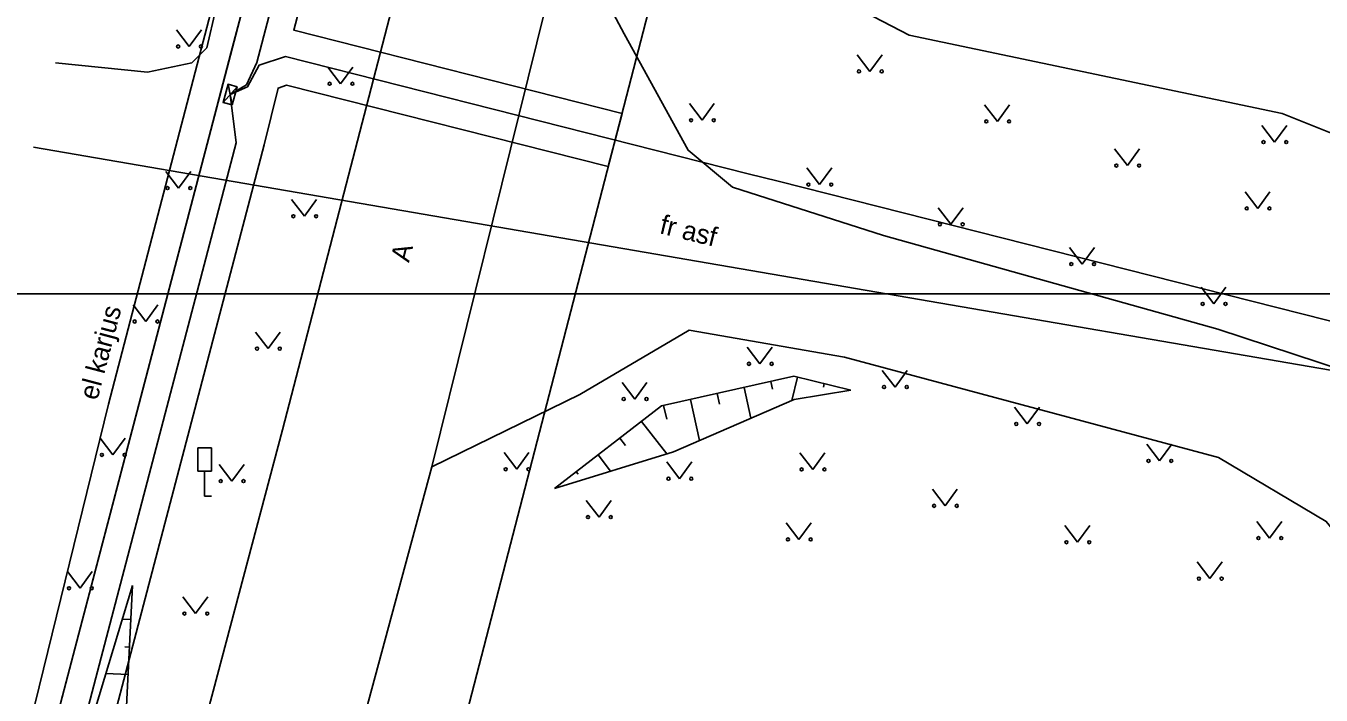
# Model space of a CAD drawing. Extents: x 554947 to 555436, y 6564938 to 6565792.
# Drawn here: x 555148.42 to 555195.59, y 6565133.31 to 6565157.67 of the extents above; entities that cross this region are included whole.
import ezdxf

# ---------------------------------------------------------------- set-up
doc = ezdxf.new("R2010")
doc.units = 0
for name, color, linetype in [('AED', 7, 'Continuous'), ('HALJASTUS', 7, 'Continuous'), ('KASUTUSALA', 7, 'Continuous'), ('KPKAABEL', 7, 'Continuous'), ('KPOHULIIN', 7, 'Continuous'), ('LIIKLUS', 7, 'Continuous'), ('PIIR', 7, 'Continuous'), ('PR_SIDE', 7, 'Continuous'), ('RELJEEF', 7, 'Continuous'), ('TEE', 7, 'Continuous'), ('VORMISTUS_1', 7, 'Continuous')]:
    doc.layers.add(name, color=color, linetype=linetype)

msp = doc.modelspace()

# ---------------------------------------------------------------- linework, layer by layer
at = {"layer": 'AED'}
msp.add_lwpolyline([(555179.37, 6565300.078), (555180.242, 6565299.846), (555180.75, 6565290.874), (555180.137, 6565280.616), (555178.982, 6565264.788), (555177.984, 6565255.288), (555177.306, 6565249.05), (555173.486, 6565227.422), (555169.733, 6565212.423), (555163.779, 6565189.534), (555156.086, 6565161.758), (555151.428, 6565143.905), (555146.995, 6565125.891), (555142.273, 6565107.514), (555136.767, 6565086.759), (555131.214, 6565064.984), (555128.386, 6565056.617), (555127.142, 6565056.522)], dxfattribs=at)
at = {"layer": 'HALJASTUS'}
for p, q in [((555153.905, 6565157.527), (555154.369, 6565156.92)), ((555154.369, 6565156.92), (555154.814, 6565157.527)), ((555178.697, 6565156.621), (555179.16, 6565156.014)), ((555179.16, 6565156.014), (555179.606, 6565156.621)), ((555159.422, 6565156.171), (555159.885, 6565155.564)), ((555159.885, 6565155.564), (555160.331, 6565156.171)), ((555172.582, 6565154.843), (555173.046, 6565154.237)), ((555173.046, 6565154.237), (555173.491, 6565154.843)), ((555183.335, 6565154.799), (555183.798, 6565154.192)), ((555183.798, 6565154.192), (555184.244, 6565154.799)), ((555193.428, 6565154.044), (555193.891, 6565153.438)), ((555193.891, 6565153.438), (555194.337, 6565154.044)), ((555188.069, 6565153.192), (555188.533, 6565152.586)), ((555188.533, 6565152.586), (555188.978, 6565153.192)), ((555176.858, 6565152.501), (555177.321, 6565151.895)), ((555177.321, 6565151.895), (555177.767, 6565152.501)), ((555153.519, 6565152.37), (555153.983, 6565151.764)), ((555153.983, 6565151.764), (555154.428, 6565152.37)), ((555192.817, 6565151.631), (555193.281, 6565151.024)), ((555193.281, 6565151.024), (555193.726, 6565151.631)), ((555158.1, 6565151.349), (555158.563, 6565150.742)), ((555158.563, 6565150.742), (555159.009, 6565151.349)), ((555181.643, 6565151.053), (555182.107, 6565150.447)), ((555182.107, 6565150.447), (555182.552, 6565151.053)), ((555186.429, 6565149.605), (555186.892, 6565148.998)), ((555186.892, 6565148.998), (555187.338, 6565149.605)), ((555191.215, 6565148.157), (555191.678, 6565147.55)), ((555191.678, 6565147.55), (555192.124, 6565148.157)), ((555152.323, 6565147.515), (555152.787, 6565146.909)), ((555152.787, 6565146.909), (555153.232, 6565147.515)), ((555156.778, 6565146.526), (555157.241, 6565145.92)), ((555157.241, 6565145.92), (555157.687, 6565146.526)), ((555174.691, 6565145.974), (555175.155, 6565145.368)), ((555175.155, 6565145.368), (555175.6, 6565145.974)), ((555179.609, 6565145.131), (555180.072, 6565144.524)), ((555180.072, 6565144.524), (555180.518, 6565145.131)), ((555170.131, 6565144.692), (555170.594, 6565144.086)), ((555170.594, 6565144.086), (555171.04, 6565144.692)), ((555184.425, 6565143.785), (555184.888, 6565143.179)), ((555184.888, 6565143.179), (555185.334, 6565143.785)), ((555151.127, 6565142.66), (555151.591, 6565142.054)), ((555151.591, 6565142.054), (555152.036, 6565142.66)), ((555165.834, 6565142.136), (555166.297, 6565141.53)), ((555166.297, 6565141.53), (555166.743, 6565142.136)), ((555176.61, 6565142.129), (555177.073, 6565141.523)), ((555177.073, 6565141.523), (555177.519, 6565142.129)), ((555189.24, 6565142.44), (555189.703, 6565141.833)), ((555189.703, 6565141.833), (555190.149, 6565142.44)), ((555155.456, 6565141.704), (555155.919, 6565141.098)), ((555155.919, 6565141.098), (555156.365, 6565141.704)), ((555171.761, 6565141.794), (555172.224, 6565141.187)), ((555172.224, 6565141.187), (555172.67, 6565141.794)), ((555181.431, 6565140.804), (555181.895, 6565140.198)), ((555181.895, 6565140.198), (555182.34, 6565140.804)), ((555168.829, 6565140.394), (555169.293, 6565139.788)), ((555169.293, 6565139.788), (555169.738, 6565140.394)), ((555176.111, 6565139.581), (555176.574, 6565138.974)), ((555176.574, 6565138.974), (555177.02, 6565139.581)), ((555186.252, 6565139.479), (555186.716, 6565138.872)), ((555186.716, 6565138.872), (555187.161, 6565139.479)), ((555193.244, 6565139.631), (555193.707, 6565139.024)), ((555193.707, 6565139.024), (555194.152, 6565139.631)), ((555191.074, 6565138.154), (555191.537, 6565137.547)), ((555191.537, 6565137.547), (555191.983, 6565138.154)), ((555149.932, 6565137.806), (555150.395, 6565137.199)), ((555150.395, 6565137.199), (555150.841, 6565137.806)), ((555154.134, 6565136.882), (555154.598, 6565136.276)), ((555154.598, 6565136.276), (555155.043, 6565136.882))]:
    msp.add_line(p, q, dxfattribs=at)
msp.add_lwpolyline([(555170.849, 6565163.433), (555170.802, 6565162.422), (555180.588, 6565157.338), (555194.166, 6565154.476), (555200.547, 6565151.934), (555210.105, 6565148.383), (555222.421, 6565148.556), (555228.239, 6565151.421), (555231.104, 6565153.786)], dxfattribs=at)
for centre in [(555153.968, 6565156.92), (555154.796, 6565156.92), (555178.759, 6565156.014), (555179.588, 6565156.014), (555159.484, 6565155.564), (555160.313, 6565155.564), (555172.645, 6565154.237), (555173.473, 6565154.237), (555183.397, 6565154.192), (555184.226, 6565154.192), (555193.49, 6565153.438), (555194.319, 6565153.438), (555188.132, 6565152.586), (555188.961, 6565152.586), (555153.582, 6565151.764), (555154.41, 6565151.764), (555176.92, 6565151.895), (555177.749, 6565151.895), (555192.88, 6565151.024), (555193.708, 6565151.024), (555158.162, 6565150.742), (555158.991, 6565150.742), (555181.706, 6565150.447), (555182.534, 6565150.447), (555186.491, 6565148.998), (555187.32, 6565148.998), (555191.277, 6565147.55), (555192.106, 6565147.55), (555152.386, 6565146.909), (555153.214, 6565146.909), (555156.84, 6565145.92), (555157.669, 6565145.92), (555174.754, 6565145.368), (555175.582, 6565145.368), (555179.671, 6565144.524), (555180.5, 6565144.524), (555170.193, 6565144.086), (555171.022, 6565144.086), (555184.487, 6565143.179), (555185.316, 6565143.179), (555151.19, 6565142.054), (555152.019, 6565142.054), (555165.896, 6565141.53), (555166.725, 6565141.53), (555189.302, 6565141.833), (555190.131, 6565141.833), (555155.518, 6565141.098), (555156.347, 6565141.098), (555171.823, 6565141.187), (555172.652, 6565141.187), (555176.672, 6565141.523), (555177.501, 6565141.523), (555181.494, 6565140.198), (555182.322, 6565140.198), (555168.892, 6565139.788), (555169.721, 6565139.788), (555176.173, 6565138.974), (555177.002, 6565138.974), (555186.315, 6565138.872), (555187.144, 6565138.872), (555193.306, 6565139.024), (555194.135, 6565139.024), (555191.136, 6565137.547), (555191.965, 6565137.547), (555149.994, 6565137.199), (555150.823, 6565137.199), (555154.197, 6565136.276), (555155.025, 6565136.276)]:
    msp.add_circle(centre, 0.055, dxfattribs=at)
at = {"layer": 'KASUTUSALA'}
for points in [[(555127.058, 6565046.777), (555141.002, 6565099.93), (555152.728, 6565144.628), (555155.084, 6565153.611), (555155.888, 6565156.675), (555156.912, 6565160.576), (555162.414, 6565181.549), (555172.651, 6565220.574), (555172.7, 6565220.76), (555176.927, 6565240.07), (555176.937, 6565240.135), (555179.22, 6565254.85)], [(555181.208, 6565254.618), (555178.897, 6565239.723), (555174.645, 6565220.292), (555158.175, 6565157.509), (555170.133, 6565154.484), (555169.631, 6565152.548), (555157.917, 6565155.511), (555157.606, 6565155.409), (555157.1, 6565153.341), (555146.607, 6565113.414), (555140.881, 6565091.587), (555138.365, 6565081.691), (555135.803, 6565072.229), (555119.022, 6565008.261)]]:
    msp.add_lwpolyline(points, dxfattribs=at)
at = {"layer": 'KPKAABEL'}
msp.add_lwpolyline([(555172.536, 6565254.014), (555171.281, 6565241.464), (555170.488, 6565231.192), (555168.866, 6565217.1), (555167.048, 6565204.461), (555164.351, 6565191.399), (555161.107, 6565179.306), (555157.628, 6565168.142), (555155.008, 6565156.873), (555154.465, 6565156.331), (555152.85, 6565155.986), (555149.5, 6565156.323)], dxfattribs=at)
at = {"layer": 'KPOHULIIN'}
msp.add_lwpolyline([(555148.701, 6565153.258), (555226.644, 6565139.855), (555319.309, 6565121.586)], dxfattribs=at)
at = {"layer": 'LIIKLUS'}
for p, q in [((555154.681, 6565142.306), (555154.681, 6565141.457)), ((555155.181, 6565142.306), (555154.681, 6565142.306)), ((555155.181, 6565142.306), (555155.181, 6565141.457)), ((555155.181, 6565141.457), (555154.681, 6565141.457)), ((555154.931, 6565141.457), (555154.931, 6565140.556)), ((555155.181, 6565140.556), (555154.931, 6565140.556))]:
    msp.add_line(p, q, dxfattribs=at)
at = {"layer": 'PIIR'}
msp.add_lwpolyline([(554962.55, 6565234.93), (555180.26, 6565306.43), (555180.8, 6565287.7), (555180.41, 6565269.99), (555179.22, 6565254.85), (555176.93, 6565240.09), (555172.7, 6565220.76), (555117.14, 6565008.97), (555108.27, 6564991.27)], close=True, dxfattribs=at)
for points in [[(555195.28, 6565271.63), (555191.64, 6565237.48), (555173.84, 6565168.77), (555173.21, 6565166.35), (555172.58, 6565163.93), (555140.74, 6565041.04), (555133.32, 6565012.53), (555119.68, 6564972.95), (555107.79, 6564965.53), (555093.78, 6564958.98), (555080.97, 6564954.71), (555029.586, 6564944.201)], [(555029.586, 6564962.189), (555076.32, 6564971.61), (555087.28, 6564975.26), (555098.22, 6564980.37), (555106.03, 6564987.06), (555108.27, 6564991.27), (555117.14, 6565008.97), (555172.7, 6565220.76), (555176.93, 6565240.09), (555179.22, 6565254.85)], [(555272.013, 6565013.369), (555140.74, 6565041.04), (555172.58, 6565163.93), (555173.21, 6565166.35), (555225.89, 6565157.13), (555231.12, 6565150.64), (555239.11, 6565139), (555273.15, 6565087.34), (555275.41, 6565088.83), (555288.85, 6565092.31), (555289.83, 6565088.53), (555290.166, 6565088.221)]]:
    msp.add_lwpolyline(points, dxfattribs=at)
at = {"layer": 'PR_SIDE'}
for p, q in [((555156.116, 6565155.457), (555155.601, 6565154.883)), ((555155.934, 6565154.792), (555155.784, 6565155.548))]:
    msp.add_line(p, q, dxfattribs=at)
for points in [[(555210.992, 6564988.671), (555132.015, 6564980.717), (555127.536, 6564982.26), (555122.65, 6564985.013), (555110.837, 6564991.67), (555110.25, 6564992.989), (555118.081, 6565008.615), (555124.872, 6565034.501), (555128.062, 6565046.662), (555134.837, 6565072.487), (555137.397, 6565081.944), (555139.913, 6565091.837), (555145.64, 6565113.668), (555156.083, 6565153.408), (555155.859, 6565155.17), (555156.452, 6565155.519), (555156.834, 6565156.34), (555160.763, 6565171.317), (555163.707, 6565182.54), (555165.376, 6565188.901), (555173.672, 6565220.526), (555176.862, 6565235.1), (555177.913, 6565239.906), (555180.214, 6565254.734)], [(555239.586, 6565136.265), (555231.314, 6565137.915), (555222.994, 6565144.574), (555217.72, 6565147.16), (555203.944, 6565144.9), (555175.818, 6565152.015), (555174.729, 6565152.29), (555157.882, 6565156.552), (555156.917, 6565156.236), (555156.491, 6565155.453), (555155.859, 6565155.17)]]:
    msp.add_lwpolyline(points, dxfattribs=at)
msp.add_lwpolyline([(555155.934, 6565154.792), (555156.116, 6565155.457), (555155.784, 6565155.548), (555155.601, 6565154.883)], close=True, dxfattribs=at)
at = {"layer": 'RELJEEF'}
for p, q in [((555174.573, 6565144.51), (555174.824, 6565143.386)), ((555175.549, 6565144.729), (555175.612, 6565144.448)), ((555176.524, 6565144.881), (555176.32, 6565144.035)), ((555177.496, 6565144.646), (555177.467, 6565144.524)), ((555172.621, 6565144.074), (555172.956, 6565142.576)), ((555173.597, 6565144.292), (555173.685, 6565143.899)), ((555171.645, 6565143.855), (555171.758, 6565143.35)), ((555170.84, 6565143.274), (555171.757, 6565142.086)), ((555170.048, 6565142.663), (555170.255, 6565142.396)), ((555169.257, 6565142.052), (555169.716, 6565141.458)), ((555168.465, 6565141.44), (555168.534, 6565141.351)), ((555152.292, 6565137.054), (555152.273, 6565137.055)), ((555152.242, 6565136.056), (555151.932, 6565136.071)), ((555152.192, 6565135.057), (555152.024, 6565135.065)), ((555152.142, 6565134.058), (555151.334, 6565134.099))]:
    msp.add_line(p, q, dxfattribs=at)
for points in [[(555167.674, 6565140.829), (555171.571, 6565143.839), (555176.382, 6565144.915), (555178.457, 6565144.415)], [(555167.674, 6565140.829), (555172, 6565142.161), (555176.401, 6565144.071), (555178.457, 6565144.415)], [(555119.659, 6565010.325), (555123.707, 6565025.312), (555129.009, 6565045.265), (555134.764, 6565064.612), (555140.243, 6565085.297), (555145.723, 6565106.564), (555150.38, 6565124.533), (555151.998, 6565131.189), (555152.304, 6565137.301)], [(555119.659, 6565010.325), (555122.574, 6565025.466), (555127.459, 6565046.429), (555133.335, 6565064.856), (555138.641, 6565085.815), (555144.363, 6565106.834), (555149.086, 6565124.763), (555150.576, 6565131.594), (555152.304, 6565137.301)]]:
    msp.add_lwpolyline(points, dxfattribs=at)
at = {"layer": 'TEE'}
for points in [[(555183.594, 6565248.995), (555179.697, 6565227.862), (555175.388, 6565210.507), (555169.433, 6565187.479), (555162.32, 6565160.507), (555157.772, 6565142.96), (555152.674, 6565123.751), (555148.003, 6565106.069), (555142.307, 6565084.705), (555136.784, 6565063.937), (555131.82, 6565044.704), (555126.529, 6565024.437), (555123.003, 6565010.821), (555119.083, 6564999.093), (555116.16, 6564993.195), (555108.256, 6564982.259)], [(555114.997, 6564980.207), (555119.473, 6564986.791), (555121.429, 6564990.442), (555124.132, 6564996.667), (555128.448, 6565009.121), (555131.982, 6565022.769), (555137.234, 6565043.213), (555142.087, 6565062.036), (555147.465, 6565082.979), (555153.125, 6565104.459), (555157.981, 6565122.311), (555163.2, 6565141.618), (555168.3, 6565162.209), (555168.744, 6565163.563), (555174.483, 6565185.521), (555180.709, 6565208.971), (555185.087, 6565226.838), (555186.799, 6565233.51), (555187.911, 6565235.651)], [(555205.86, 6565133.779), (555206.217, 6565135.824), (555207.407, 6565138.329), (555209.429, 6565140.104), (555211.794, 6565141.192), (555217.229, 6565143.067), (555216.442, 6565145.526), (555210.771, 6565144.283), (555206.511, 6565143.557), (555202.006, 6565143.277), (555191.831, 6565146.626), (555179.65, 6565150.043), (555174.155, 6565151.803), (555172.54, 6565153.141), (555170.207, 6565157.377), (555168.463, 6565160.669), (555168.3, 6565162.209)], [(555163.2, 6565141.618), (555168.594, 6565144.246), (555172.571, 6565146.598), (555178.227, 6565145.611), (555191.847, 6565141.953), (555195.778, 6565139.63), (555200.739, 6565133.541)]]:
    msp.add_lwpolyline(points, dxfattribs=at)
at = {"layer": 'VORMISTUS_1'}
msp.add_lwpolyline([(555035.188, 6565444.913), (555245.188, 6565444.913), (555245.188, 6565147.913), (555035.188, 6565147.913)], close=True, dxfattribs=at)

# ---------------------------------------------------------------- texts
at = {"layer": 'AED'}
msp.add_text('el karjus', height=0.7, rotation=75.2255, dxfattribs=at).set_placement((555151.021, 6565144.012))
at = {"layer": 'TEE'}
for s, rotation, p in [('fr asf', 346.2302, (555171.463, 6565150.126)), ('A', 75.6331, (555162.372, 6565149.033))]:
    msp.add_text(s, height=0.7, rotation=rotation, dxfattribs=at).set_placement(p)

doc.saveas('drawing.dxf')
